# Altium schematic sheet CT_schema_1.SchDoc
size 473 x 258 mm
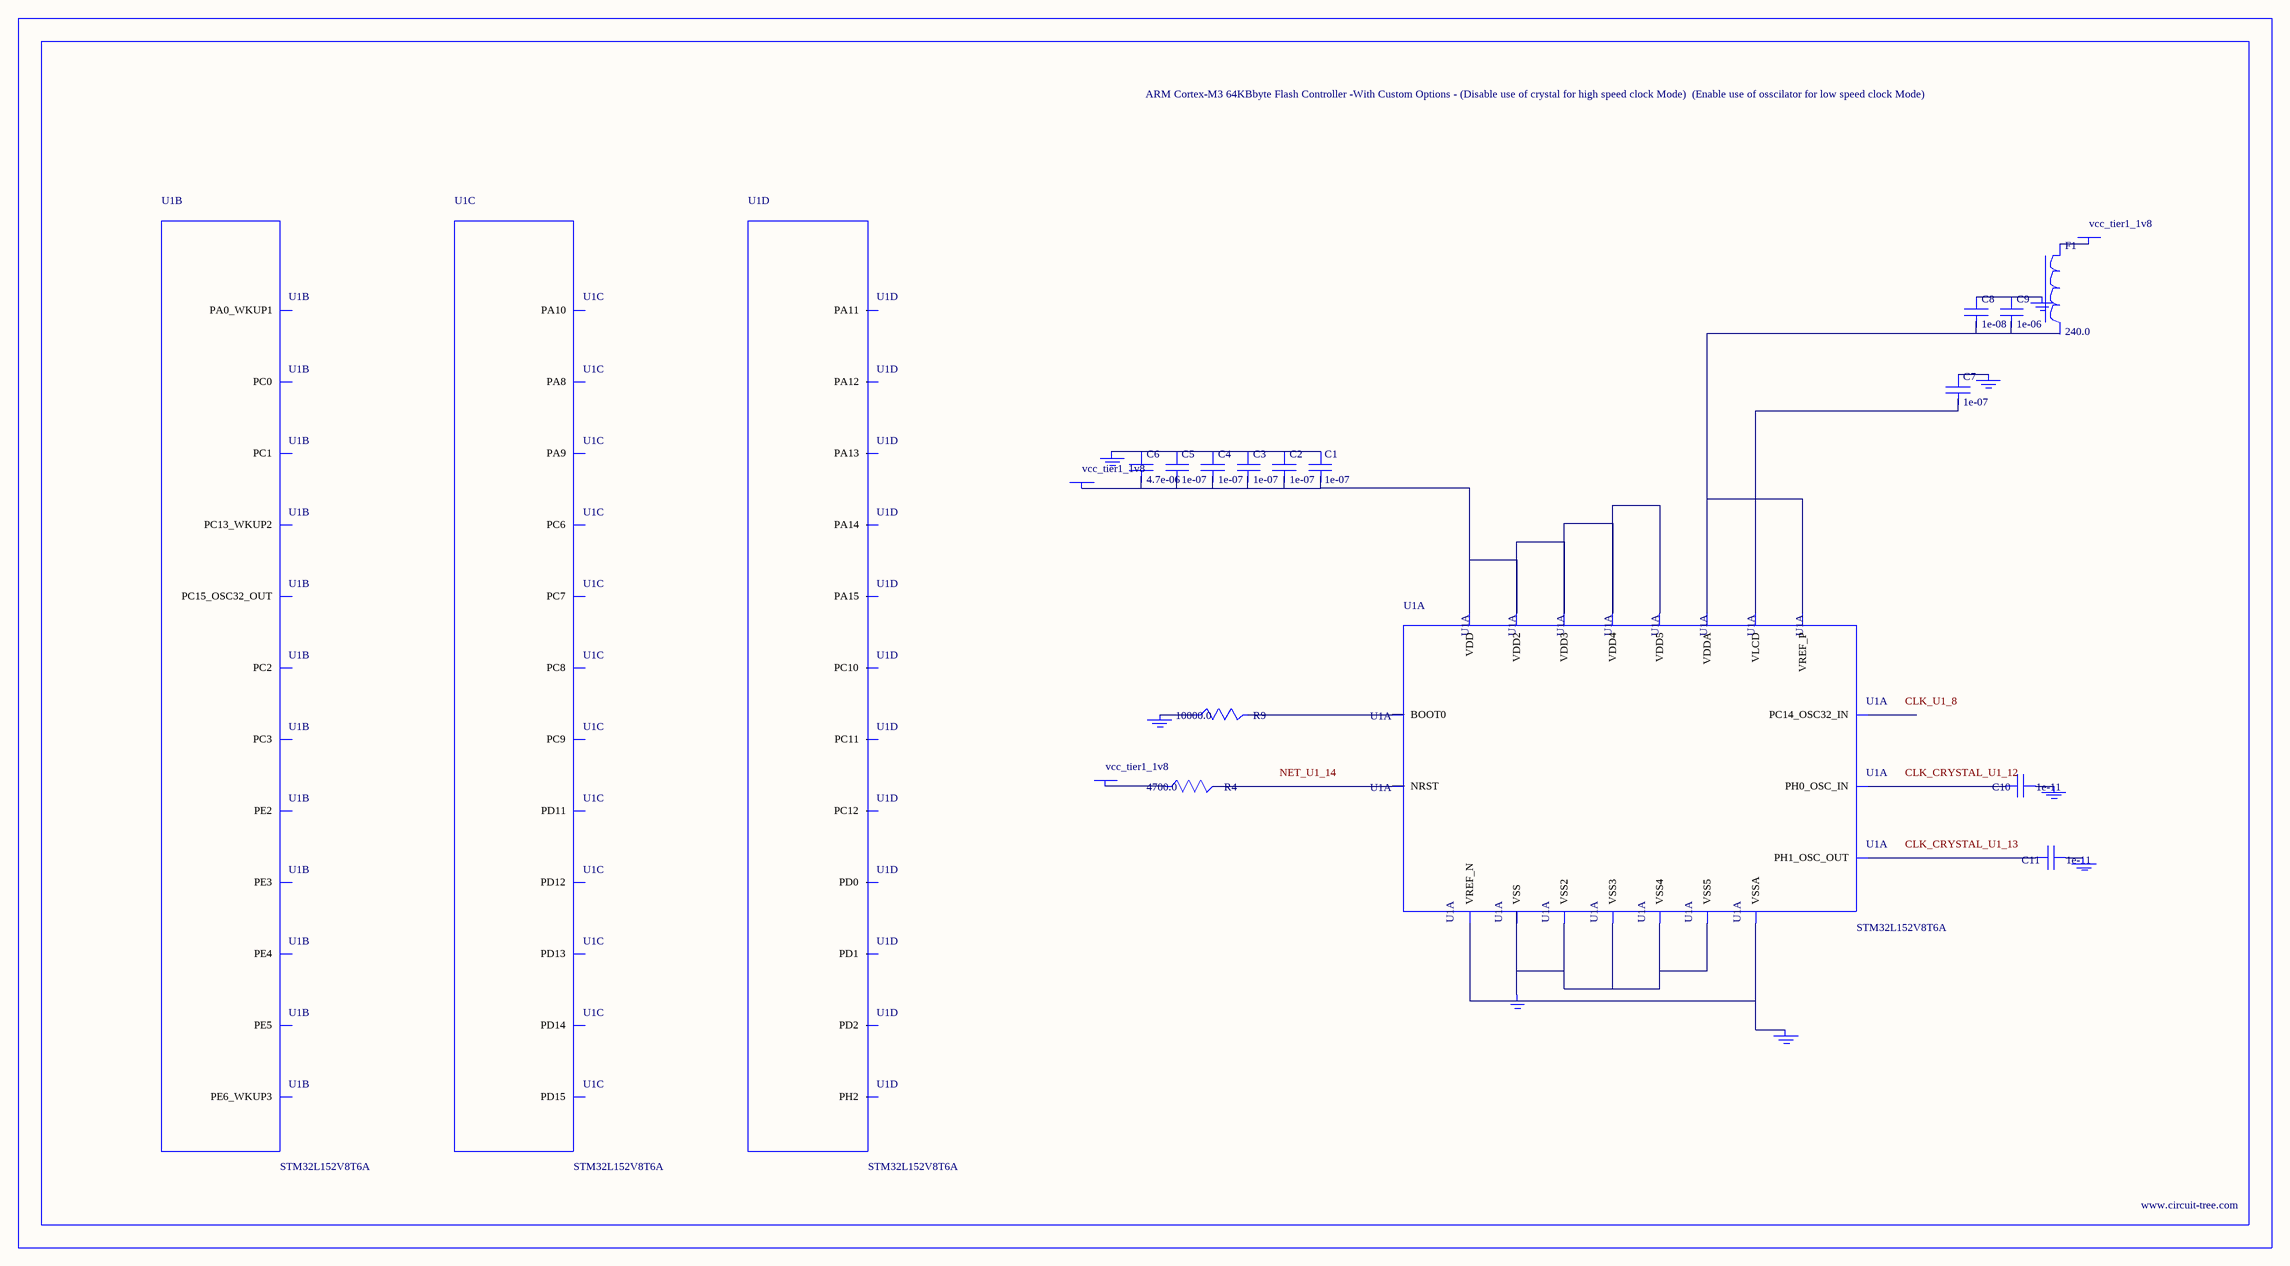
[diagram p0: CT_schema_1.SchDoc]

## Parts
BORDER0  (no value)
C1  1e-07  [C0603]
C2  1e-07  [C0603]
C3  1e-07  [C0603]
C4  1e-07  [C0603]
C5  1e-07  [C0603]
C6  4.7e-06  [C0603]
C7  1e-07  [C0603]
C8  1e-08  [C0603]
C9  1e-06  [C0603]
C10  1e-11  [C0402]
C11  1e-11  [C0402]
F1  240.0  [L0603]
GND_INSTANCE_0_0  (no value)
GND_INSTANCE_0_1  (no value)
GND_INSTANCE_0_2  (no value)
GND_INSTANCE_0_3  (no value)
GND_INSTANCE_0_4  (no value)
GND_INSTANCE_0_5  (no value)
GND_INSTANCE_0_6  (no value)
GND_INSTANCE_0_7  (no value)
POWER_INSTANCE_0_0  vcc_tier1_1v8
POWER_INSTANCE_0_1  vcc_tier1_1v8
POWER_INSTANCE_0_2  vcc_tier1_1v8
R4  4700.0  [R0603]
R9  10000.0  [R0603]
U1  STM32L152V8T6A  [LQFP100]  (parts A,B,C,D of 9)

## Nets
NetC1_1: C1.1 C2.1 C3.1 C4.1 C5.1 C6.1 GND_INSTANCE_0_1.0(GND)
NetC1_2: C1.2 C2.2 C3.2 C4.2 C5.2 C6.2 POWER_INSTANCE_0_0.0(PWR) U1.11(VDD) U1.28(VDD2) U1.50(VDD3) U1.75(VDD4) U1.100(VDD5)
NetC7_1: C7.1 GND_INSTANCE_0_0.0(GND)
NetC7_2: C7.2 U1.6(VLCD)
NetC8_1: C8.1 C9.1 GND_INSTANCE_0_5.0(GND)
NetC8_2: C8.2 C9.2 U1.21(VREF_P) U1.22(VDDA)
NetC10_1: C10.1 GND_INSTANCE_0_2.0(GND)
NetC10_2: C10.2 U1.12(PH0_OSC_IN)
NetC11_1: C11.1 GND_INSTANCE_0_3.0(GND)
NetC11_2: C11.2 U1.13(PH1_OSC_OUT)
NetF1_1: F1.1 POWER_INSTANCE_0_1.0(PWR)
NetGND_INSTANCE_0_4_0: GND_INSTANCE_0_4.0(GND) U1.19(VSSA) U1.20(VREF_N)
NetGND_INSTANCE_0_6_0: GND_INSTANCE_0_6.0(GND) R9.1
NetGND_INSTANCE_0_7_0: GND_INSTANCE_0_7.0(GND) U1.10(VSS) U1.27(VSS2) U1.49(VSS3) U1.74(VSS4) U1.99(VSS5)
NetPOWER_INSTANCE_0_2_0: POWER_INSTANCE_0_2.0(PWR) R4.1
NetR4_2: R4.2 U1.14(NRST)
NetR9_2: R9.2 U1.94(BOOT0)

Not connected (* = marked no-connect by the designer): F1 2; U1 1(PE2) 2(PE3) 3(PE4) 4(PE5) 5(PE6_WKUP3) 7(PC13_WKUP2) 8(PC14_OSC32_IN) 9(PC15_OSC32_OUT) 15(PC0) 16(PC1) 17(PC2) 18(PC3) 23(PA0_WKUP1) 58(PD11) 59(PD12) 60(PD13) 61(PD14) 62(PD15) 63(PC6) 64(PC7) 65(PC8) 66(PC9) 67(PA8) 68(PA9) 69(PA10) 70(PA11) 71(PA12) 72(PA13) 73(PH2) 76(PA14) 77(PA15) 78(PC10) 79(PC11) 80(PC12) 81(PD0) 82(PD1) 83(PD2)

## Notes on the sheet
- Labels drawn without touching a wire or pin: CLK_CRYSTAL_U1_12, CLK_CRYSTAL_U1_13, CLK_U1_8, NET_U1_14

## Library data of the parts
BORDER0 = BORDER_PAGE0
C1-C5 C7 = 06035C104K4Z2A
C6 = GRM188R6YA475KE15D
C8 = 06035C103K4Z2A
C9 = C0603C105K3RACTU
C10 C11 = C0402C100K3GACTU
F1 = Z0603C241ASMST
GND_INSTANCE_0_0-GND_INSTANCE_0_7 = GND
POWER_INSTANCE_0_0-POWER_INSTANCE_0_2 = PWR
R4 = RC0603JR-074K7L
R9 = RC0603JR-0710KL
